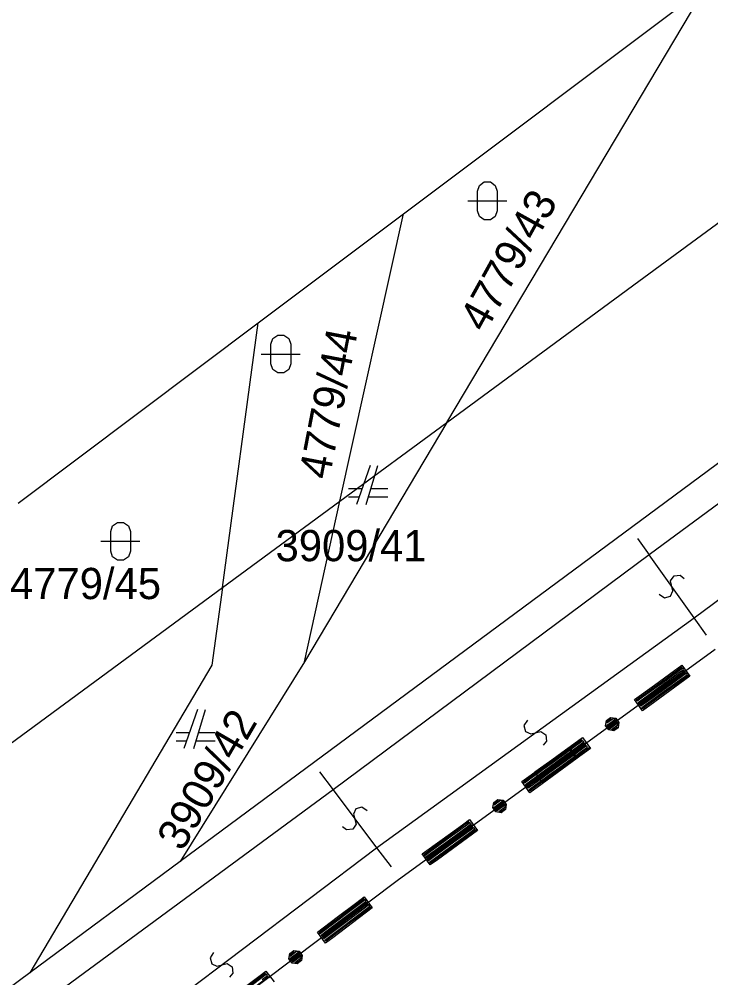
# Model space of a CAD drawing. Extents: x -266179 to -264727, y -1243225 to -1241702.
# Drawn here: x -265235.19 to -265199.76, y -1242855.08 to -1242805.99 of the extents above; entities that cross this region are included whole.
import ezdxf

# ---------------------------------------------------------------- set-up
doc = ezdxf.new("R2010")
doc.units = 0
for name, color, linetype in [('Vrstva 1', 7, 'Continuous'), ('Vrstva 19', 7, 'Continuous'), ('Vrstva 2', 7, 'Continuous'), ('Vrstva 21', 7, 'Continuous')]:
    doc.layers.add(name, color=color, linetype=linetype)

msp = doc.modelspace()

# ---------------------------------------------------------------- linework, layer by layer
at = {"layer": 'Vrstva 1'}
for p, q in [((-265203.44, -1242819.41), (-265176.4, -1242799.52)), ((-265215.5, -1242815.96), (-265200, -1242804.33)), ((-265213.28, -1242826.64), (-265200, -1242804.33)), ((-265222.95, -1242821.55), (-265215.5, -1242815.96)), ((-265218.76, -1242830.67), (-265215.5, -1242815.96)), ((-265213.28, -1242826.64), (-265203.44, -1242819.41)), ((-265235.24, -1242830.77), (-265222.95, -1242821.55)), ((-265224.78, -1242835.1), (-265222.95, -1242821.55)), ((-265213.28, -1242826.64), (-265220.58, -1242838.91)), ((-265218.76, -1242830.67), (-265213.28, -1242826.64)), ((-265198.21, -1242827.87), (-265226.94, -1242849.13)), ((-265217.21, -1242828.85), (-265217.91, -1242830.85)), ((-265217.41, -1242830.85), (-265216.81, -1242828.85)), ((-265217.63, -1242830.05), (-265218.31, -1242830.05)), ((-265216.31, -1242830.05), (-265217.17, -1242830.05)), ((-265224.78, -1242835.1), (-265218.76, -1242830.67)), ((-265220.58, -1242838.91), (-265218.76, -1242830.67)), ((-265218.31, -1242830.45), (-265217.77, -1242830.45)), ((-265217.29, -1242830.45), (-265216.31, -1242830.45)), ((-265247.08, -1242851.49), (-265224.78, -1242835.1)), ((-265224.78, -1242835.1), (-265225.32, -1242839.08)), ((-265199.54, -1242838.27), (-265215.83, -1242850.11)), ((-265225.32, -1242839.08), (-265234.64, -1242854.83)), ((-265220.58, -1242838.91), (-265226.94, -1242849.13)), ((-265226.05, -1242841.34), (-265226.75, -1242843.34)), ((-265226.25, -1242843.34), (-265225.65, -1242841.34)), ((-265226.47, -1242842.54), (-265227.15, -1242842.54)), ((-265227.15, -1242842.94), (-265226.61, -1242842.94)), ((-265226.13, -1242842.94), (-265225.15, -1242842.94)), ((-265225.15, -1242842.54), (-265226.01, -1242842.54)), ((-265226.94, -1242849.13), (-265234.64, -1242854.83)), ((-265215.83, -1242850.11), (-265231.75, -1242862.11)), ((-265234.64, -1242854.83), (-265241.32, -1242859.77))]:
    msp.add_line(p, q, dxfattribs=at)
for points in [[(-265211.71, -1242814.8), (-265211.61, -1242814.51), (-265211.36, -1242814.33), (-265211.05, -1242814.33), (-265210.8, -1242814.51), (-265210.7, -1242814.8), (-265210.7, -1242815.8), (-265210.8, -1242816.09), (-265211.05, -1242816.27), (-265211.36, -1242816.27), (-265211.61, -1242816.09), (-265211.71, -1242815.8)], [(-265222.29, -1242822.64), (-265222.19, -1242822.35), (-265221.94, -1242822.17), (-265221.63, -1242822.17), (-265221.38, -1242822.35), (-265221.28, -1242822.64), (-265221.28, -1242823.64), (-265221.38, -1242823.93), (-265221.63, -1242824.11), (-265221.94, -1242824.11), (-265222.19, -1242823.93), (-265222.29, -1242823.64)], [(-265230.5, -1242832.23), (-265230.4, -1242831.94), (-265230.15, -1242831.76), (-265229.84, -1242831.76), (-265229.59, -1242831.94), (-265229.49, -1242832.23), (-265229.49, -1242833.23), (-265229.59, -1242833.52), (-265229.84, -1242833.7), (-265230.15, -1242833.7), (-265230.4, -1242833.52), (-265230.5, -1242833.23)]]:
    msp.add_lwpolyline(points, close=True, dxfattribs=at)
for points in [[(-265212.21, -1242815.3), (-265210.94, -1242815.3), (-265210.21, -1242815.3)], [(-265222.79, -1242823.14), (-265221.52, -1242823.14), (-265220.79, -1242823.14)], [(-265231, -1242832.73), (-265229.73, -1242832.73), (-265229, -1242832.73)]]:
    msp.add_lwpolyline(points, dxfattribs=at)
at = {"layer": 'Vrstva 19'}
for p, q in [((-265199.54, -1242838.27), (-265215.83, -1242850.11)), ((-265215.83, -1242850.11), (-265231.75, -1242862.11))]:
    msp.add_line(p, q, dxfattribs=at)
for points in [[(-265200.83, -1242839.641), (-265201.858, -1242840.388), (-265202.885, -1242841.134), (-265203.257, -1242841.405), (-265203.669, -1242840.838), (-265202.641, -1242840.092), (-265201.614, -1242839.345), (-265201.242, -1242839.075), (-265200.83, -1242839.641), (-265200.912, -1242839.614), (-265201.939, -1242840.361), (-265202.967, -1242841.107), (-265203.242, -1242841.307), (-265203.289, -1242841.242), (-265202.262, -1242840.496), (-265201.234, -1242839.749), (-265200.959, -1242839.549), (-265201.006, -1242839.485), (-265202.034, -1242840.231), (-265203.061, -1242840.978), (-265203.336, -1242841.178), (-265203.383, -1242841.113), (-265202.356, -1242840.366), (-265201.328, -1242839.62), (-265201.053, -1242839.42), (-265201.1, -1242839.355), (-265202.128, -1242840.102), (-265203.155, -1242840.848), (-265203.43, -1242841.048), (-265203.477, -1242840.983), (-265202.45, -1242840.237), (-265201.422, -1242839.49), (-265201.147, -1242839.29), (-265201.194, -1242839.226), (-265202.222, -1242839.972), (-265203.249, -1242840.719), (-265203.524, -1242840.919), (-265203.571, -1242840.854), (-265202.544, -1242840.107), (-265201.516, -1242839.361), (-265201.241, -1242839.161)], [(-265204.505, -1242842.274), (-265204.723, -1242842.433), (-265204.988, -1242842.391), (-265205.147, -1242842.172), (-265205.105, -1242841.907), (-265204.887, -1242841.748), (-265204.621, -1242841.79), (-265204.463, -1242842.009), (-265204.505, -1242842.274), (-265204.536, -1242842.248), (-265204.73, -1242842.389), (-265204.842, -1242842.371), (-265204.519, -1242842.136), (-265204.501, -1242842.024), (-265204.954, -1242842.353), (-265205.001, -1242842.289), (-265204.548, -1242841.959), (-265204.595, -1242841.895), (-265205.048, -1242842.224), (-265205.095, -1242842.159), (-265204.642, -1242841.83), (-265204.754, -1242841.812), (-265205.077, -1242842.047), (-265205.06, -1242841.936), (-265204.865, -1242841.795)], [(-265205.927, -1242843.345), (-265206.954, -1242844.091), (-265207.982, -1242844.838), (-265208.354, -1242845.108), (-265208.765, -1242844.542), (-265207.738, -1242843.795), (-265206.711, -1242843.049), (-265206.338, -1242842.778), (-265205.927, -1242843.345), (-265206.025, -1242843.329), (-265207.052, -1242844.076), (-265208.079, -1242844.822), (-265208.355, -1242845.022), (-265208.402, -1242844.958), (-265207.374, -1242844.211), (-265206.347, -1242843.464), (-265206.072, -1242843.264), (-265206.119, -1242843.2), (-265207.146, -1242843.946), (-265208.174, -1242844.693), (-265208.449, -1242844.893), (-265208.496, -1242844.828), (-265207.468, -1242844.082), (-265206.441, -1242843.335), (-265206.166, -1242843.135), (-265206.213, -1242843.07), (-265207.24, -1242843.817), (-265208.268, -1242844.563), (-265208.543, -1242844.763), (-265208.59, -1242844.699), (-265207.562, -1242843.952), (-265206.535, -1242843.205), (-265206.26, -1242843.006), (-265206.307, -1242842.941), (-265207.334, -1242843.687), (-265208.362, -1242844.434), (-265208.637, -1242844.634), (-265208.684, -1242844.569), (-265207.656, -1242843.823), (-265206.629, -1242843.076), (-265206.354, -1242842.876)], [(-265206.605, -1242843.838), (-265207.632, -1242844.585), (-265208.659, -1242845.331), (-265209.032, -1242845.602), (-265209.443, -1242845.035), (-265208.416, -1242844.289), (-265207.388, -1242843.542), (-265207.016, -1242843.272), (-265206.605, -1242843.838), (-265206.686, -1242843.811), (-265207.714, -1242844.557), (-265208.741, -1242845.304), (-265209.016, -1242845.504), (-265209.063, -1242845.439), (-265208.036, -1242844.693), (-265207.008, -1242843.946), (-265206.733, -1242843.746), (-265206.78, -1242843.681), (-265207.808, -1242844.428), (-265208.835, -1242845.175), (-265209.11, -1242845.374), (-265209.157, -1242845.31), (-265208.13, -1242844.563), (-265207.102, -1242843.817), (-265206.827, -1242843.617), (-265206.874, -1242843.552), (-265207.902, -1242844.298), (-265208.929, -1242845.045), (-265209.204, -1242845.245), (-265209.251, -1242845.18), (-265208.224, -1242844.434), (-265207.196, -1242843.687), (-265206.921, -1242843.487), (-265206.968, -1242843.422), (-265207.996, -1242844.169), (-265209.023, -1242844.916), (-265209.298, -1242845.116), (-265209.345, -1242845.051), (-265208.318, -1242844.304), (-265207.291, -1242843.558), (-265207.015, -1242843.358)], [(-265210.279, -1242846.471), (-265210.497, -1242846.63), (-265210.763, -1242846.588), (-265210.921, -1242846.369), (-265210.879, -1242846.104), (-265210.661, -1242845.945), (-265210.396, -1242845.987), (-265210.237, -1242846.205), (-265210.279, -1242846.471), (-265210.31, -1242846.444), (-265210.505, -1242846.585), (-265210.616, -1242846.568), (-265210.293, -1242846.333), (-265210.275, -1242846.221), (-265210.728, -1242846.55), (-265210.775, -1242846.485), (-265210.322, -1242846.156), (-265210.369, -1242846.091), (-265210.822, -1242846.421), (-265210.869, -1242846.356), (-265210.416, -1242846.027), (-265210.528, -1242846.009), (-265210.851, -1242846.244), (-265210.834, -1242846.132), (-265210.64, -1242845.991)], [(-265211.701, -1242847.542), (-265212.729, -1242848.288), (-265213.756, -1242849.035), (-265214.128, -1242849.305), (-265214.54, -1242848.739), (-265213.512, -1242847.992), (-265212.485, -1242847.246), (-265212.113, -1242846.975), (-265211.701, -1242847.542), (-265211.799, -1242847.526), (-265212.826, -1242848.273), (-265213.854, -1242849.019), (-265214.129, -1242849.219), (-265214.176, -1242849.154), (-265213.148, -1242848.408), (-265212.121, -1242847.661), (-265211.846, -1242847.461), (-265211.893, -1242847.397), (-265212.92, -1242848.143), (-265213.948, -1242848.89), (-265214.223, -1242849.09), (-265214.27, -1242849.025), (-265213.242, -1242848.278), (-265212.215, -1242847.532), (-265211.94, -1242847.332), (-265211.987, -1242847.267), (-265213.014, -1242848.014), (-265214.042, -1242848.76), (-265214.317, -1242848.96), (-265214.364, -1242848.895), (-265213.336, -1242848.149), (-265212.309, -1242847.402), (-265212.034, -1242847.202), (-265212.081, -1242847.138), (-265213.108, -1242847.884), (-265214.136, -1242848.631), (-265214.411, -1242848.831), (-265214.458, -1242848.766), (-265213.431, -1242848.019), (-265212.403, -1242847.273), (-265212.128, -1242847.073)], [(-265217.098, -1242851.501), (-265218.112, -1242852.266), (-265219.125, -1242853.031), (-265219.493, -1242853.308), (-265219.914, -1242852.749), (-265218.901, -1242851.984), (-265217.887, -1242851.219), (-265217.52, -1242850.942), (-265217.098, -1242851.501), (-265217.18, -1242851.475), (-265218.194, -1242852.24), (-265219.208, -1242853.005), (-265219.479, -1242853.21), (-265219.527, -1242853.146), (-265218.513, -1242852.381), (-265217.5, -1242851.616), (-265217.228, -1242851.411), (-265217.276, -1242851.348), (-265218.29, -1242852.113), (-265219.304, -1242852.878), (-265219.575, -1242853.082), (-265219.624, -1242853.018), (-265218.61, -1242852.253), (-265217.596, -1242851.489), (-265217.325, -1242851.284), (-265217.373, -1242851.22), (-265218.387, -1242851.985), (-265219.4, -1242852.75), (-265219.672, -1242852.955), (-265219.72, -1242852.891), (-265218.706, -1242852.126), (-265217.692, -1242851.361), (-265217.421, -1242851.156), (-265217.469, -1242851.092), (-265218.483, -1242851.857), (-265219.497, -1242852.622), (-265219.768, -1242852.827), (-265219.816, -1242852.763), (-265218.802, -1242851.998), (-265217.789, -1242851.233), (-265217.517, -1242851.028)], [(-265220.724, -1242854.2), (-265220.94, -1242854.362), (-265221.206, -1242854.325), (-265221.368, -1242854.11), (-265221.331, -1242853.843), (-265221.116, -1242853.681), (-265220.849, -1242853.718), (-265220.687, -1242853.934), (-265220.724, -1242854.2), (-265220.756, -1242854.174), (-265220.948, -1242854.318), (-265221.06, -1242854.303), (-265220.74, -1242854.062), (-265220.725, -1242853.95), (-265221.172, -1242854.287), (-265221.22, -1242854.223), (-265220.773, -1242853.886), (-265220.821, -1242853.822), (-265221.268, -1242854.159), (-265221.316, -1242854.095), (-265220.869, -1242853.758), (-265220.981, -1242853.742), (-265221.301, -1242853.983), (-265221.285, -1242853.871), (-265221.093, -1242853.727)], [(-265223.93, -1242855.779), (-265222.916, -1242855.014), (-265222.549, -1242854.737), (-265222.127, -1242855.296)], [(-265223.847, -1242855.805), (-265222.834, -1242855.04), (-265222.562, -1242854.835)], [(-265222.737, -1242855.168), (-265222.466, -1242854.963), (-265222.514, -1242854.899), (-265223.528, -1242855.664)], [(-265222.369, -1242855.09), (-265222.418, -1242855.027), (-265223.431, -1242855.792)]]:
    msp.add_lwpolyline(points, dxfattribs=at)
at = {"layer": 'Vrstva 2'}
for p, q in [((-265186.95, -1242821.6), (-265202.91, -1242833.43)), ((-265200.61, -1242836.64), (-265184.56, -1242824.81)), ((-265203.52, -1242832.58), (-265202.91, -1242833.43)), ((-265202.91, -1242833.43), (-265219.11, -1242845.45)), ((-265200.61, -1242836.64), (-265202.91, -1242833.43)), ((-265216.88, -1242848.42), (-265200.61, -1242836.64)), ((-265199.97, -1242837.54), (-265200.61, -1242836.64)), ((-265219.8, -1242844.54), (-265219.11, -1242845.45)), ((-265219.11, -1242845.45), (-265235.14, -1242857.24)), ((-265219.11, -1242845.45), (-265216.88, -1242848.42)), ((-265232.76, -1242860.42), (-265216.88, -1242848.42)), ((-265216.88, -1242848.42), (-265216.14, -1242849.4))]:
    msp.add_line(p, q, dxfattribs=at)
for points in [[(-265202.399, -1242835.431), (-265202.129, -1242835.619), (-265201.821, -1242835.534), (-265201.699, -1242835.274), (-265201.828, -1242834.751), (-265201.642, -1242834.495), (-265201.33, -1242834.468), (-265201.121, -1242834.639)], [(-265209.145, -1242841.893), (-265209.331, -1242842.164), (-265209.244, -1242842.472), (-265208.984, -1242842.592), (-265208.462, -1242842.461), (-265208.205, -1242842.645), (-265208.176, -1242842.957), (-265208.345, -1242843.167)], [(-265217.365, -1242846.525), (-265217.639, -1242846.343), (-265217.945, -1242846.435), (-265218.061, -1242846.697), (-265217.921, -1242847.217), (-265218.101, -1242847.477), (-265218.413, -1242847.511), (-265218.625, -1242847.345)], [(-265225.232, -1242853.791), (-265225.413, -1242854.066), (-265225.32, -1242854.372), (-265225.058, -1242854.487), (-265224.538, -1242854.345), (-265224.278, -1242854.524), (-265224.243, -1242854.836), (-265224.408, -1242855.049)]]:
    msp.add_lwpolyline(points, dxfattribs=at)
at = {"layer": 'Vrstva 21'}
for p, q in [((-265199.54, -1242838.27), (-265215.83, -1242850.11)), ((-265215.83, -1242850.11), (-265231.75, -1242862.11))]:
    msp.add_line(p, q, dxfattribs=at)

# ---------------------------------------------------------------- texts
at = {"layer": 'Vrstva 1'}
for s, rotation, p in [('4779/43', 61.02, (-265211.314, -1242822.097)), ('4779/44', 79.1255, (-265219.301, -1242829.612)), ('3909/42', 59.8741, (-265226.832, -1242848.662))]:
    msp.add_text(s, height=1.6, rotation=rotation, dxfattribs=at).set_placement(p)
for s, p in [('3909/41', (-265222.054, -1242833.75)), ('4779/45', (-265235.657, -1242835.69))]:
    msp.add_text(s, height=1.6, dxfattribs=at).set_placement(p)

doc.saveas('drawing.dxf')
